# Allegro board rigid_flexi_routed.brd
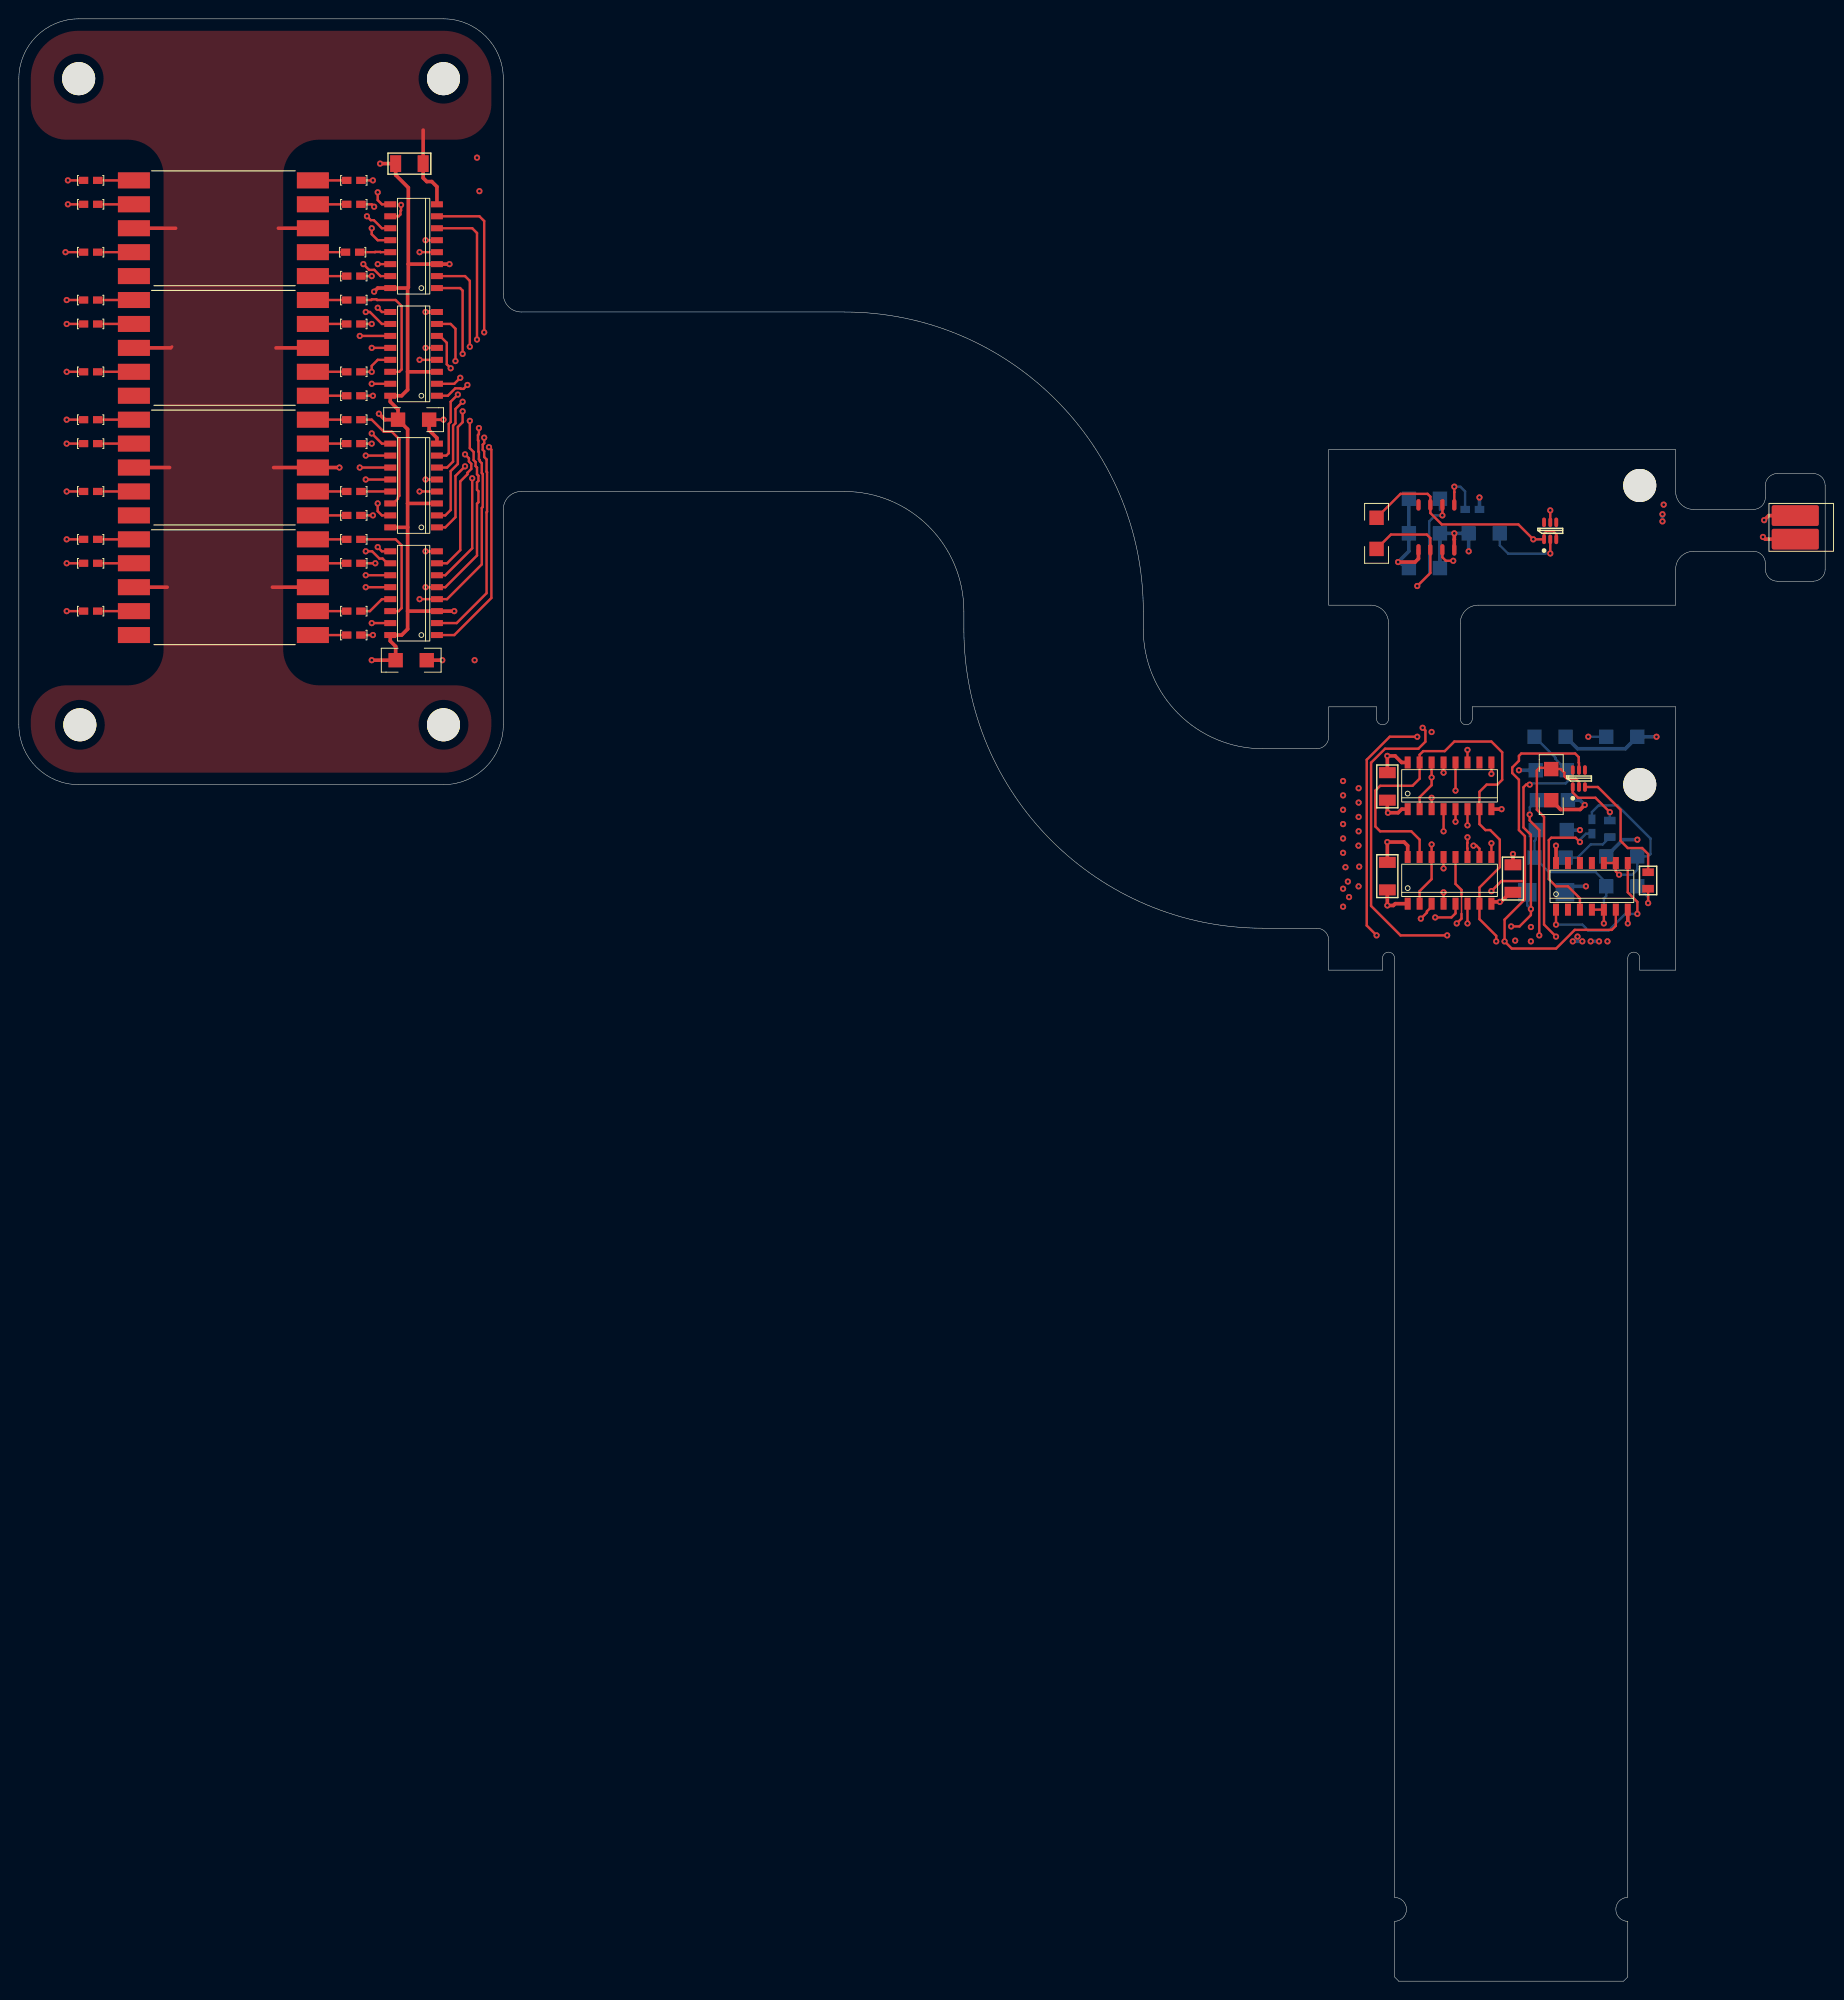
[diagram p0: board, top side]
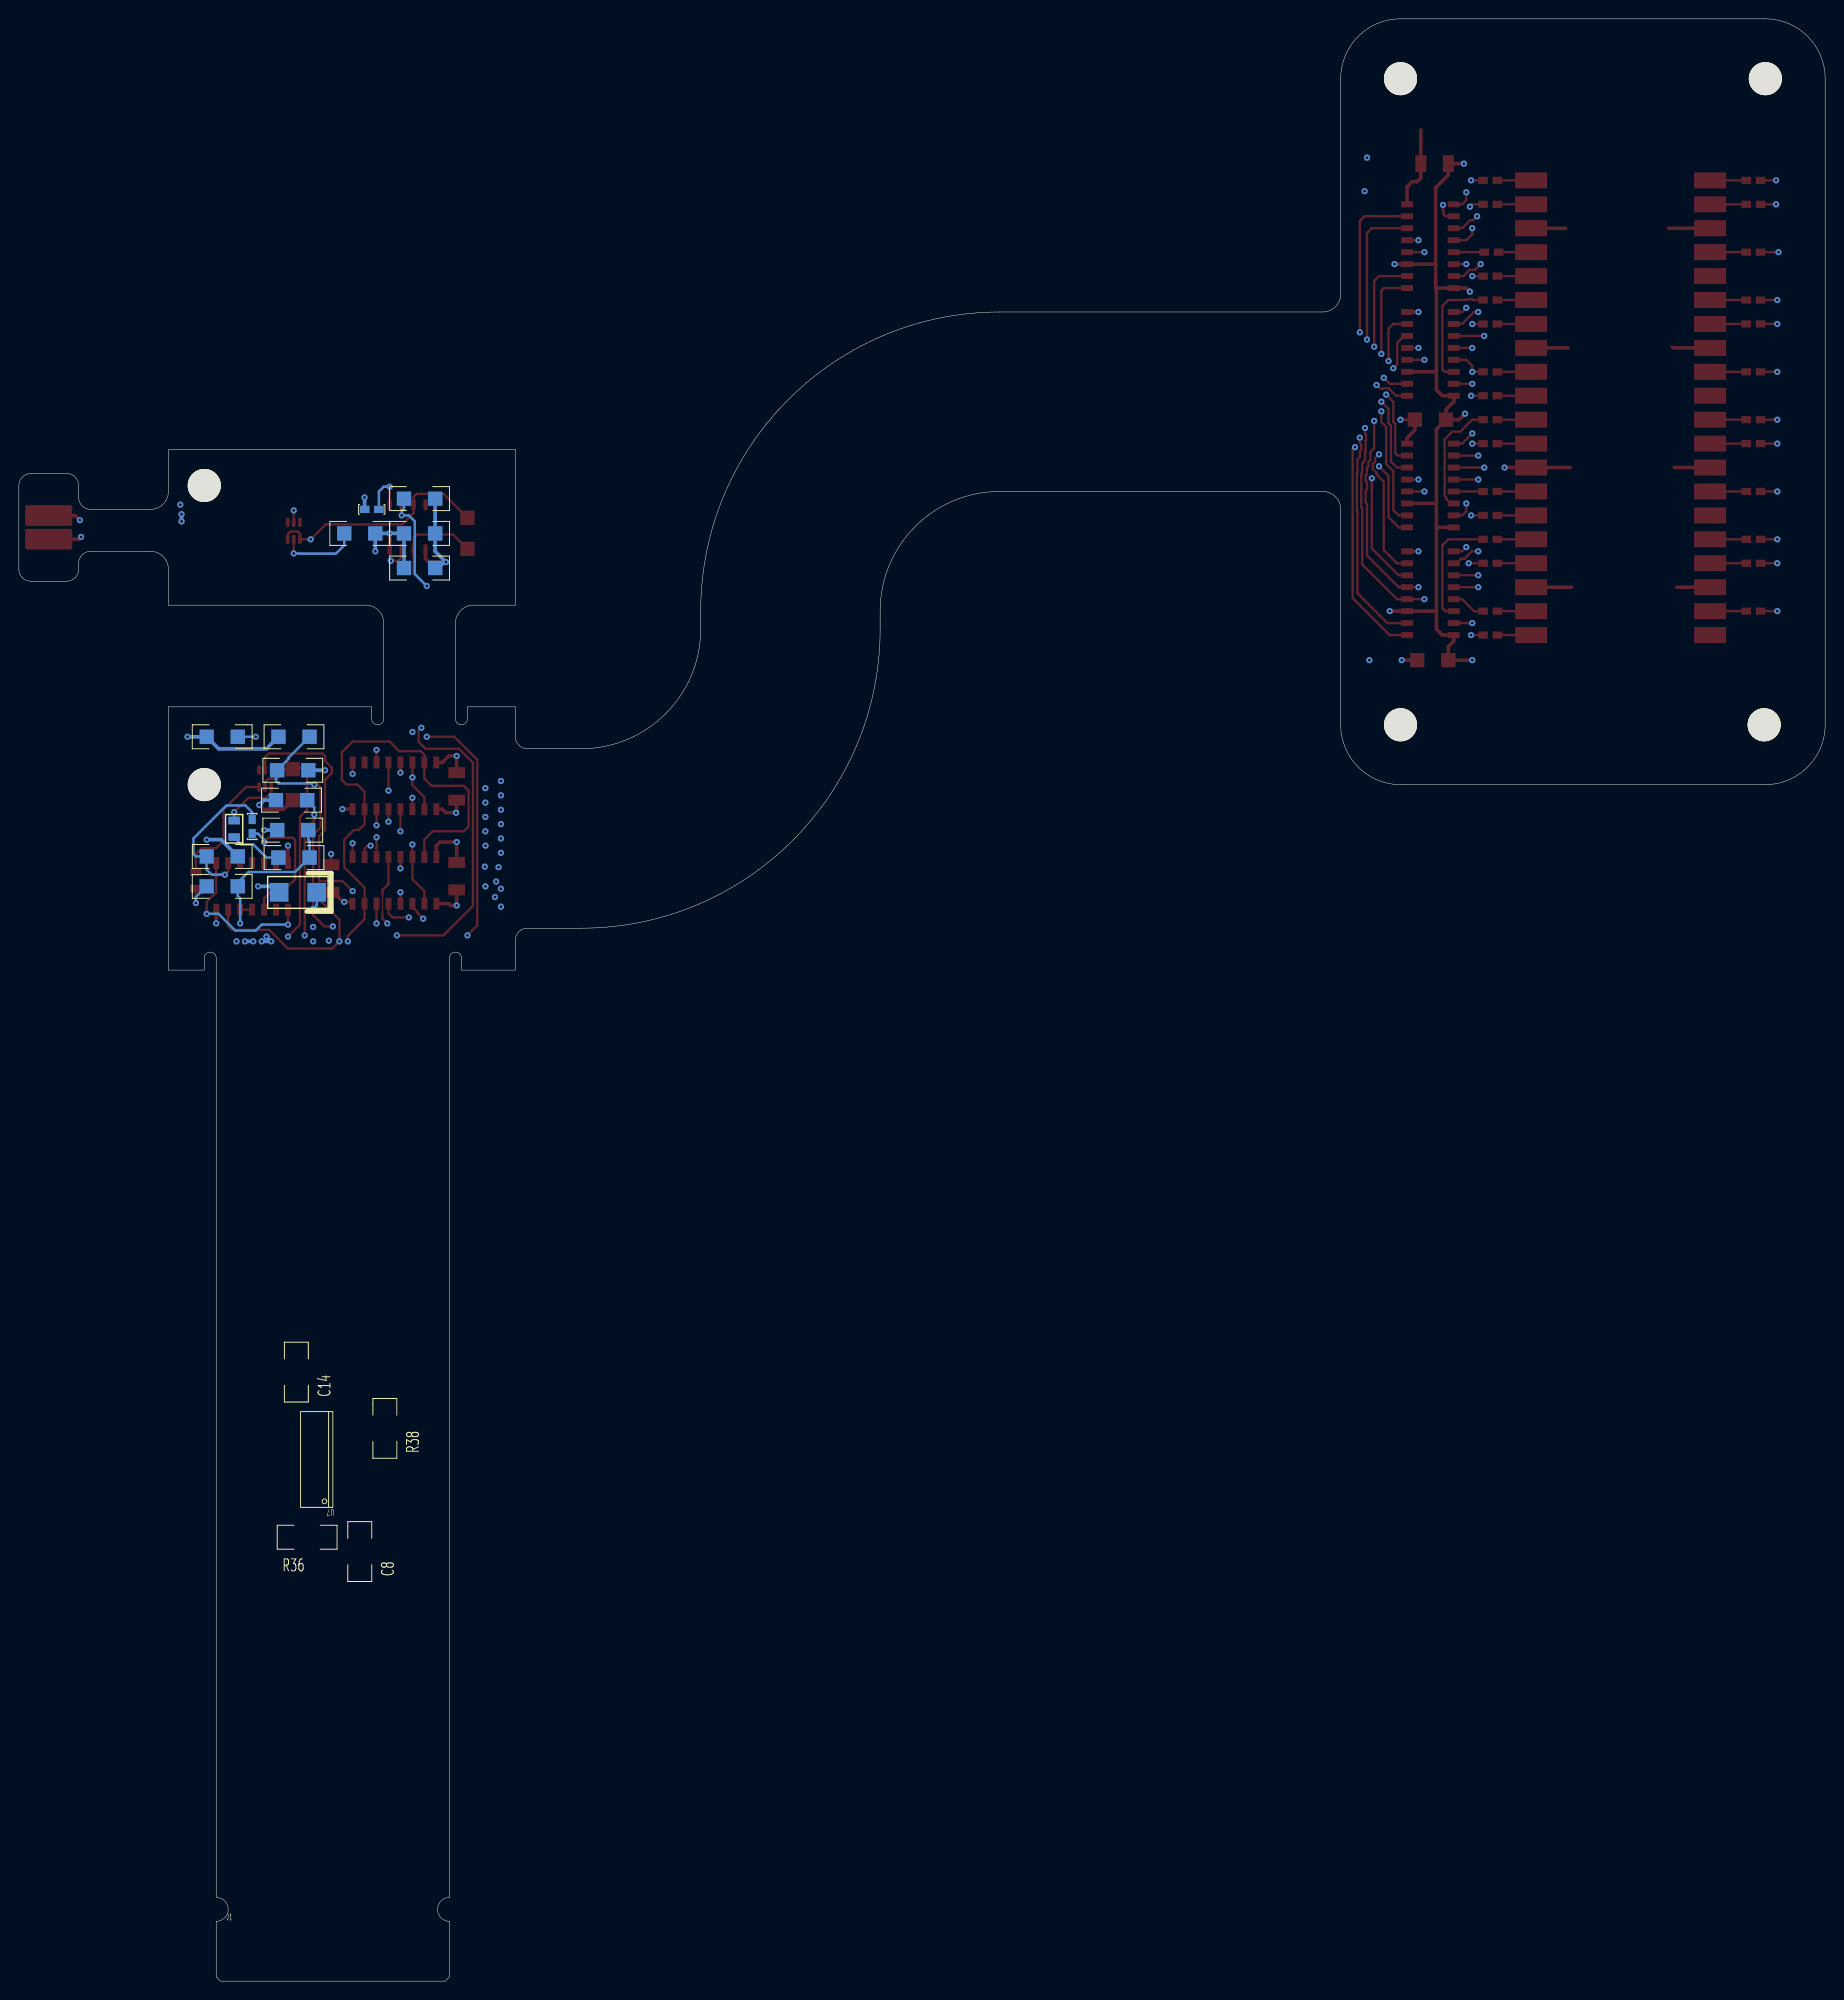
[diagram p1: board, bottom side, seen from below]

Outline 191.77 x 208.28 mm; copper layers: TOP, INT_1, FLEX_1, FLEX_2, INT_4, BOTTOM. Coordinates in mm from the lower left corner of the outline.
Outline path: 0,201.93 0,133.35 arc(1.86,128.86) 6.35,127 45.08,127 arc(49.58,128.86) 51.43,133.35 51.43,156.21 arc(51.99,157.56) 53.34,158.12 87.63,158.12 arc(96.61,154.4) 100.33,145.41 100.33,143.51 arc(109.63,121.06) 132.08,111.76 137.8,111.76 arc(138.69,111.39) 139.06,110.49 139.06,107.31 144.78,107.31 144.78,108.59 arc(145.41,109.22) 146.05,108.59 146.05,8.89 arc(147.32,7.62) 146.05,6.35 146.05,0.45 146.5,0 170.37,0 170.81,0.45 170.81,6.35 arc(169.55,7.62) 170.81,8.89 170.81,108.59 arc(171.45,109.22) 172.08,108.59 172.08,107.31 175.89,107.31 175.89,135.25 154.31,135.25 154.31,133.99 arc(153.67,133.35) 153.03,133.99 153.03,144.14 arc(153.59,145.49) 154.94,146.05 175.89,146.05 175.89,149.86 arc(176.45,151.21) 177.8,151.76 184.15,151.76 arc(185.05,151.39) 185.42,150.5 185.42,149.86 arc(185.79,148.96) 186.69,148.59 190.5,148.59 arc(191.4,148.96) 191.77,149.86 191.77,158.75 arc(191.4,159.65) 190.5,160.02 186.69,160.02 arc(185.79,159.65) 185.42,158.75 185.42,157.48 arc(185.05,156.58) 184.15,156.21 177.8,156.21 arc(176.45,156.77) 175.89,158.12 175.89,162.56 139.06,162.56 139.06,146.05 143.51,146.05 arc(144.86,145.49) 145.41,144.14 145.41,133.99 arc(144.78,133.35) 144.14,133.99 144.14,135.25 139.06,135.25 139.06,132.08 arc(138.69,131.18) 137.8,130.81 132.08,130.81 arc(123.1,134.53) 119.38,143.51 119.38,145.41 arc(110.08,167.87) 87.63,177.17 53.34,177.17 arc(51.99,177.72) 51.43,179.07 51.43,201.93 arc(49.58,206.42) 45.08,208.28 6.35,208.28 arc(1.86,206.42) 0,201.93

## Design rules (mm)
constraint set DEFAULT: min track width 0.254
nets with their own width: min track width 0.381; nets GND

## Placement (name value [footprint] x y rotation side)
B1  -  [BATT1]  188.59 154.31 90 top
C1  -  [A_MC-1206_A]  145.29 115.82 90 top
C2  -  [A_MC-1206_A]  145.29 125.35 90 top
C3  -  [A_MC-1206_A]  158.62 115.57 90 top
C4  -  [A_MC-1206_A]  42.93 192.91 180 top
C5  .001UF  [1206RF_WV_12D]  149.22 149.99 180 bottom
C6  .001UF  [1206RF_WV_12D]  149.22 153.67 180 bottom
C7  .001UF  [1206RF_WV_12D]  149.22 157.35 0 bottom
C8  .001UF  [1206RF_WV_12D#2]  155.57 45.59 90 bottom
C9  .001UF  [1206RF_WV_12D]  162.69 122.17 0 bottom
C10  .001UF  [1206RF_WV_12D]  41.91 165.74 0 top
C11  .001UF  [1206RF_WV_12D]  41.66 140.21 180 top
C12  .1UF  [0603RF_WV_12D]  154.31 156.21 180 bottom
C13  .1UF  [0603RF_WV_12D]  167 122.56 270 bottom
C14  10UF  [1206RF_WV_12D#2]  162.31 64.64 90 bottom
C15  10UF  [1206RF_WV_12D]  162.69 128.52 180 bottom
D1  1N4148  [A_CR-0805]  168.91 123.19 270 bottom
D2  1N4148  [A_CR-0805]  172.97 115.95 90 top
D3  20V  [A_DIODE-157]  160.15 115.57 0 bottom
DSP1  -  [LED-DISPLAY]  21.72 186.06 270 top
DSP2  -  [LED-DISPLAY]  21.72 173.36 270 top
DSP3  -  [LED-DISPLAY]  21.72 160.66 270 top
DSP4  -  [LED-DISPLAY]  21.72 147.95 270 top
J1  -  [CONN10]  169.8 3.56 180 bottom
NOREF  -  [unnamed]  172.08 127 0 top
NOREF#2  -  [unnamed]  6.48 133.35 0 top
NOREF#3  -  [unnamed]  45.08 201.93 0 top
NOREF#4  -  [unnamed]  172.08 158.75 0 top
NOREF#5  -  [unnamed]  45.08 133.35 0 top
NOREF#6  -  [unnamed]  6.35 201.93 0 top
R1  390  [0603RF_WV_12D]  7.62 191.13 0 top
R2  390  [0603RF_WV_12D]  35.56 191.13 0 top
R3  390  [0603RF_WV_12D]  7.62 188.59 0 top
R4  390  [0603RF_WV_12D]  35.56 188.59 0 top
R5  390  [0603RF_WV_12D]  7.62 183.51 0 top
R6  390  [0603RF_WV_12D]  35.43 183.51 0 top
R7  390  [0603RF_WV_12D]  35.56 180.97 0 top
R8  390  [0603RF_WV_12D]  7.62 178.44 0 top
R9  390  [0603RF_WV_12D]  35.56 178.44 0 top
R10  390  [0603RF_WV_12D]  7.62 175.89 0 top
R11  390  [0603RF_WV_12D]  35.56 175.89 0 top
R12  390  [0603RF_WV_12D]  7.62 170.81 0 top
R13  390  [0603RF_WV_12D]  35.56 170.81 0 top
R14  390  [0603RF_WV_12D]  35.56 168.28 0 top
R15  390  [0603RF_WV_12D]  7.62 165.74 0 top
R16  390  [0603RF_WV_12D]  35.56 165.74 0 top
R17  390  [0603RF_WV_12D]  7.62 163.19 0 top
R18  390  [0603RF_WV_12D]  35.56 163.19 0 top
R19  390  [0603RF_WV_12D]  7.62 158.12 0 top
R20  390  [0603RF_WV_12D]  35.56 158.12 0 top
R21  390  [0603RF_WV_12D]  35.56 155.57 0 top
R22  390  [0603RF_WV_12D]  7.62 153.03 0 top
R23  390  [0603RF_WV_12D]  35.56 153.03 0 top
R24  390  [0603RF_WV_12D]  7.62 150.5 0 top
R25  390  [0603RF_WV_12D]  35.56 150.5 0 top
R26  390  [0603RF_WV_12D]  7.62 145.41 0 top
R27  390  [0603RF_WV_12D]  35.56 145.41 0 top
R28  390  [0603RF_WV_12D]  35.56 142.88 0 top
R29  15K  [1206RF_WV_12D]  170.18 116.2 180 bottom
R30  15K  [1206RF_WV_12D]  162.56 119.25 180 bottom
R31  10K  [1206RF_WV_12D]  144.14 153.67 270 top
R32  10K  [1206RF_WV_12D]  155.57 153.67 0 bottom
R33  10K  [1206RF_WV_12D]  162.69 127 90 top
R34  10K  [1206RF_WV_12D]  170.18 119.38 0 bottom
R35  10K  [1206RF_WV_12D]  162.56 132.08 0 bottom
R36  100K  [1206RF_WV_12D#2]  161.16 47.12 180 bottom
R37  100K  [1206RF_WV_12D]  162.81 125.35 180 bottom
R38  12K  [1206RF_WV_12D#2]  152.91 58.67 90 bottom
R39  3.3K  [1206RF_WV_12D]  170.18 132.08 180 bottom
RV1  10K  [A_SOT363]  164.97 126.75 0 top
RV2  10K  [A_SOT363]  161.93 153.03 0 top
U1  ***  [SOIC16]  41.91 184.15 180 top
U2  ***  [SOIC16]  41.91 172.72 180 top
U3  ***  [SOIC16]  41.91 158.75 180 top
U4  ***  [SOIC16]  41.91 147.32 180 top
U5  ***  [SOIC16]  151.89 126.87 90 top
U6  ***  [SOIC16]  151.89 116.84 90 top
U7  -  [SOIC16#2]  160.15 55.37 0 bottom
U8  -  [SOIC8]  150.5 154.31 90 top
U9  ***  [SOIC14]  167.64 116.2 90 top

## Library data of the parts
B1 = BATT1
C1-C4 = CAP15UF
C5-C11 = CAP: tolerance: 10%
C12-C15 = CAP
D1 D2 = 1N4148
D3 = 20V-RCT
DSP1-DSP4 = DISPLAY-LED
J1 = CONN10
R1-R28 = RES_RES0201_DISCRETE_0.3 MM_10K
R29-R39 = RES: tolerance: 5%
RV1 RV2 = VRES
U1-U4 = CD4511
U5 U6 = CD4518
U7 = CD4098: User Part Number: ***; Tolerance: ***
U8 = NE555
U9 = SN7400

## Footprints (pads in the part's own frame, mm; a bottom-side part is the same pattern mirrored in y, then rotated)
0603RF_WV_12D
  rect 1.016x0.762 smd: 1(-0.762,0) 2(0.762,0)
1206RF_WV_12D
  rect 1.524x1.524 smd: 1(-1.651,0) 2(1.651,0)
A_CR-0805
  rect 0.813x1.219 smd: 1(0,0) 2(1.753,0)
A_DIODE-157
  rect 1.981x1.981 smd: 1(0,0) 2(3.988,0)
A_MC-1206_A
  rect 1.168x1.778 smd: 1(0,0) 2(2.921,0)
A_SOT363
  custom 0.102x0.102 smd: 1(0,0) 2(0.66,0) 3(1.295,0) 4(1.295,1.803) 5(0.66,1.803) 6(0,1.803)
BATT1
  rrect 2.2x5 smd: 1(-1.25,0) 2(1.25,0)
LED-DISPLAY
  rect 1.7x3.4 smd: 1(-5.08,-9.5) 2(-2.54,-9.5) 3(0,-9.5) 4(2.54,-9.5) 5(5.08,-9.5) 6(5.08,9.5) 7(2.54,9.5) 8(0,9.5) 9(-2.54,9.5) 10(-5.08,9.5)
SOIC8
  oval 1.23x0.46 smd: 1(-2.39,1.9) 2(-2.39,0.64) 3(-2.39,-0.63) 4(-2.39,-1.9) 5(2.39,-1.9) 6(2.39,-0.64) 7(2.39,0.64) 8(2.39,1.9)
SOIC14
  rect 1.27x0.635 smd: 1(-2.477,4.445) 2(-2.477,3.175) 3(-2.477,1.905) 4(-2.477,0.635) 5(-2.477,-0.635) 6(-2.477,-1.905) 7(-2.477,-3.175) 8(2.477,-3.175) 9(2.477,-1.905) 10(2.477,-0.635) 11(2.477,0.635) 12(2.477,1.905) 13(2.477,3.175) 14(2.477,4.445)
SOIC16
  rect 1.27x0.635 smd: 1(-2.477,4.445) 2(-2.477,3.175) 3(-2.477,1.905) 4(-2.477,0.635) 5(-2.477,-0.635) 6(-2.477,-1.905) 7(-2.477,-3.175) 8(-2.477,-4.445) 9(2.477,-4.445) 10(2.477,-3.175) 11(2.477,-1.905) 12(2.477,-0.635) 13(2.477,0.635) 14(2.477,1.905) 15(2.477,3.175) 16(2.477,4.445)
unnamed
  round 3.505 hole 3.505 unplated: (0,0)

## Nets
GND: B1.2 C1.1 C2.1 C3.1 C4.1 C5.2 C6.2 C7.1 C9.2 C10.2 C11.1 C12.1 C15.2 D3.2 DSP1.3 DSP1.8 DSP2.3 DSP2.8 DSP3.3 DSP3.8 DSP4.3 DSP4.8 U1.8 U2.8 U3.8 U4.8 U5.1 U5.8 U6.1 U6.8 U8.1 U9.7
VCC: B1.1 C1.2 C2.2 C3.2 C4.2 C5.1 C6.1 C10.1 C11.2 R32.1 R33.1 R34.1 R35.2 R37.1 R39.1 U1.3 U1.16 U2.3 U2.16 U3.3 U3.16 U4.3 U4.16 U5.16 U6.16 U8.4 U9.14
A_1: U1.7 U5.11
A_2: U2.7 U5.3
A_3: U3.7 U6.11
A_4: U4.7 U6.3
B_1: U1.1 U5.12
B_2: U2.1 U5.4
B_3: U3.1 U6.12
B_4: U4.1 U6.4
C_1: U1.2 U5.13
C_2: U2.2 U5.5
C_3: U3.2 U6.13
C_4: U4.2 U6.5
D_1: U1.6 U5.2 U5.14
D_2: U2.6 U5.6
D_3: U3.6 U6.2 U6.14
D_4: U4.6 U6.6
F1_1: R1.1 U1.9
F1_2: R8.1 U2.9
F1_3: R15.1 U3.9
F1_4: R22.1 U4.9
F2_1: R3.1 U1.10
F2_2: R10.1 U2.10
F2_3: R17.1 U3.10
F2_4: R24.1 U4.10
F3_1: R5.1 U1.11
F3_2: R12.1 U2.11
F3_3: R19.1 U3.11
F3_4: R26.1 U4.11
F4_1: R7.2 U1.12
F4_2: R14.2 U2.12
F4_3: R21.2 U3.12
F4_4: R28.2 U4.12
F5_1: R6.2 U1.13
F5_2: R13.2 U2.13
F5_3: R20.2 U3.13
F5_4: R27.2 U4.13
F6_1: R4.2 U1.15
F6_2: R11.2 U2.15
F6_3: R18.2 U3.15
F6_4: R25.2 U4.15
F7_1: R2.2 U1.14
F7_2: R9.2 U2.14
F7_3: R16.2 U3.14
F7_4: R23.2 U4.14
INT: RV1.5 U1.4 U2.4 U3.4 U4.4 U9.6
INT3: C15.1 D3.1 R35.1
INT_N: R32.2 RV2.2
LG1: D1.1 RV1.1
LG2: D2.2 RV1.3
LG3: D1.2 R30.1
LG4: D2.1 R29.1
N1_1: DSP1.1 R1.2
N1_2: DSP2.1 R8.2
N1_3: DSP3.1 R15.2
N1_4: DSP4.1 R22.2
N2_1: DSP1.2 R3.2
N2_2: DSP2.2 R10.2
N2_3: DSP3.2 R17.2
N2_4: DSP4.2 R24.2
N3_1: DSP1.4 R5.2
N3_2: DSP2.4 R12.2
N3_3: DSP3.4 R19.2
N3_4: DSP4.4 R26.2
N4_1: DSP1.6 R7.1
N4_2: DSP2.6 R14.1
N4_3: DSP3.6 R21.1
N4_4: DSP4.6 R28.1
N5_1: DSP1.7 R6.1
N5_2: DSP2.7 R13.1
N5_3: DSP3.7 R20.1
N5_4: DSP4.7 R27.1
N6_1: DSP1.9 R4.1
N6_2: DSP2.9 R11.1
N6_3: DSP3.9 R18.1
N6_4: DSP4.9 R25.1
N7_1: DSP1.10 R2.1
N7_2: DSP2.10 R9.1
N7_3: DSP3.10 R16.1
N7_4: DSP4.10 R23.1
NET000: U1.5 U2.5 U3.5 U4.5
NET001: U5.7 U5.15 U6.7 U6.15
NET002: U8.3
NET003: C7.2 R31.2 U8.2 U8.6
NET004: U5.9 U6.9 U9.1 U9.8
NET005: C9.1 R29.2 R30.2 U9.4 U9.5
SIG_IN_N: R33.2 RV1.2
TM1: R39.2 RV2.5
TM2: R31.1 RV2.1 RV2.3 U8.7
TM3: C12.2 U8.5
TM6: R37.2
VC1: C13.2 U9.3
VC2: C13.1 R34.2 U9.9 U9.10

Pads without a net: DSP1 5; DSP2 5; DSP3 5; DSP4 5; RV1 4 6; RV2 4 6; U5 10; U6 10; U8 8; U9 2 11 12 13

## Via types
v1: diameter 0.66, hole 0.305, TOP to BOTTOM, 182 vias

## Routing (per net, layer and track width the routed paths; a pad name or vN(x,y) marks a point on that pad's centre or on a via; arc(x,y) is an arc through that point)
GND: length 95.3
  TOP w0.305: C10.2 v1(45.08,165.74) ; 16.26,173.48 16.13,173.36 ; U4.8 v1(43.18,151.76)
  TOP w0.381: v1(185.29,155.07) 185.78,155.56 B1.2 ; DSP2.8 27.3,173.36 ; U5.8 v1(157.42,124.4) ; DSP1.3 16.64,186.06 ; 27.05,160.66 DSP3.8 v1(34.04,160.66) ; U6.8 156.53,114.55 v1(157.23,114.55) 157.35,114.55 158.37,115.57 C3.1 ; DSP4.8 26.92,147.95 ; C1.1 v1(145.29,114.17) 145.94,114.17 146.13,114.36 U6.1 ; C2.1 145.29,124.08 v1(145.35,124.02) 146.43,124.02 146.81,124.4 U5.1 ; 42.93,196.47 C4.1 42.93,191.39 43.31,191.01 43.84,191.01 44.39,190.46 U1.8 ; 148.59,151.92 148.59,150.98 148.23,150.62 v1(146.43,150.62) ; C11.1 v1(44.96,140.21) ; DSP1.8 27.56,186.06 ; U2.8 v1(43.18,177.17) ; U3.8 44.39,163.79 43.56,164.62 C10.2 ; 16.13,173.36 DSP2.3 ; DSP3.3 16,160.66 ; DSP4.3 15.75,147.95 ; U9.7 v1(170.81,112.27)
  FLEX_2 w0.381: 174.5,156.02 174.5,156.4 174.88,156.78 174.88,157.35 174.62,157.1 v1(174.62,156.72)
  FLEX_2 w0.5: 162.62,57.28 161.54,57.28 ; 157.67,53.47 158.75,53.47 ; 157.67,59.82 158.75,59.82 ; 157.67,56.01 158.75,56.01 ; 162.62,54.74 161.54,54.74
  BOTTOM w0.381: C15.2 v1(159.26,128.52) ; v1(166.37,116.2) 164.9,116.2 D3.2 ; C5.2 v1(146.43,150.62) 147.57,151.76 C6.2 C7.1 ; C9.2 v1(165.74,122.17) ; v1(174.5,154.94) v1(174.5,155.7) ; C12.1 v1(155.07,157.48)
VCC: length 399.3
  TOP w0.381: C10.1 41.27,164.72 41.27,156.84 ; C10.1 40.26,166.81 39.43,167.64 39.43,168.28 40.64,168.28 41.27,168.91 41.27,170.81 ; C10.1 38.86,165.74 v1(38.23,166.37) ; C3.2 v1(158.62,119.63) ; v1(45.72,182.25) U1.3 41.35,182.25 ; 41.27,145.41 U4.3 v1(46.23,145.41) ; 41.27,145.41 41.27,154.31 ; 41.27,145.41 41.27,143.51 40.64,142.88 U4.16 39.43,142.24 40,141.67 C11.2 v1(37.46,140.21) ; 41.27,154.31 U3.16 ; 41.27,154.31 41.27,156.84 ; B1.1 185.4,153.06 v1(185.17,153.29) ; C1.2 v1(145.29,120.9) 147.07,120.9 147.45,120.52 U6.16 ; v1(166.24,124.84) 165.76,124.36 163.67,124.36 R33.1 ; U3.3 41.27,156.84 ; 41.27,170.81 U2.3 ; 41.27,170.81 41.27,179.7 ; v1(37.72,179.32) 38.1,179.7 U1.16 41.27,179.7 ; 41.27,179.7 41.35,179.78 41.35,182.25 ; v1(152.4,153.67) 152.4,153.02 152.39,153.02 152.39,151.92 ; U5.16 146.81,129.35 146.11,130.05 v1(145.29,130.05) C2.2 ; U9.14 v1(163.19,120.52) ; v1(38.35,192.91) C4.2 40,191.71 41.35,190.36 41.35,182.25
  FLEX_1 w0.5: 162.81,48.89 165.99,48.89
  FLEX_1 w1.27: 49.66,179.83 49.66,178.28 50.91,177.02 arc(52,176.19) 53.34,175.89 87.63,175.89 arc(109.18,166.97) 118.11,145.41 118.11,143.51 arc(122.2,133.63) 132.08,129.54 139.32,129.54 141.61,131.83 ; 49.15,146.05 49.15,155.19 49.66,155.7 49.66,156.72 50.42,157.48 50.42,157.66 50.65,157.89 arc(51.8,158.99) 53.34,159.38 87.63,159.38 arc(97.51,155.29) 101.6,145.41 101.6,143.51 arc(110.53,121.96) 132.08,113.03 137.8,113.03 arc(139.53,112.34) 140.33,110.66 140.35,110.64 141.86,110.74
  FLEX_2 w0.381: v1(167.77,110.36) v1(168.66,110.36) ; v1(165.99,110.36) v1(166.88,110.36)
  FLEX_2 w0.5: 162.81,47.12 162.81,50.04 162.62,50.23 162.62,50.93
  BOTTOM w0.381: C5.1 C6.1 v1(152.4,153.67) 153.92,153.67 v1(153.92,151.76) ; v1(173.86,132.08) R39.1 170.56,130.81 165.48,130.81 R35.2 ; R34.1 170.31,121.16 v1(171.83,121.16) ; v1(165.99,110.36) v1(164.97,110.36) v1(165.48,110.87) ; v1(166.88,110.36) v1(167.77,110.36) ; R37.1 165.74,125.35 v1(166.24,124.84)
  vias: v1(48.39,140.21) v1(48.64,193.55) v1(48.89,189.99)
A_1: length 153.5
  TOP w0.254: U5.11 v1(153.8,130.68) ; v1(49.4,175.01) 49.4,186.82 48.89,187.32 U1.7
  FLEX_1 w0.254: v1(140.59,127.38) 132.08,127.38 arc(120.68,132.11) 115.95,143.51 115.95,145.41 arc(107.66,165.44) 87.63,173.74 59.67,173.74 arc(59.37,173.8) 59.1,173.97 59.07,174.01 arc(58.81,174.18) 58.5,174.24 50.16,174.24 v1(49.4,175.01)
  INT_4 w0.254: v1(153.8,130.68) 153.16,131.32 142.62,131.32 140.59,129.29 v1(140.59,127.38)
A_2: length 138.7
  TOP w0.254: U5.3 v1(149.99,125.6) ; U2.7 45.85,175.89 46.35,175.39 v1(46.35,171.96)
  FLEX_1 w0.254: v1(46.35,171.96) 46.86,171.45 49.4,171.45 49.66,171.2 57.24,171.2 arc(57.55,171.13) 57.81,170.96 57.84,170.92 arc(58.1,170.75) 58.41,170.69 87.63,170.69 arc(105.5,163.29) 112.9,145.41 112.9,143.51 arc(118.52,129.95) 132.08,124.33 v1(140.59,124.33)
  INT_4 w0.254: v1(140.59,124.33) 142.75,124.33 144.02,125.6 v1(149.99,125.6)
A_3: length 144.7
  TOP w0.254: U6.11 153.8,120.22 153.77,120.25 153.77,120.8 153.8,120.82 v1(153.8,121.41) ; v1(46.61,168.4) 45.85,167.64 45.85,165.49 45.64,165.29 45.64,162.18 45.39,161.93 U3.7
  FLEX_1 w0.254: v1(46.61,168.4) 47.88,168.4 48.13,168.15 55.15,168.15 arc(55.63,168.05) 56.04,167.78 56.44,167.38 arc(56.86,167.1) 57.34,167 87.63,167 arc(103.35,160.5) 109.85,144.78 109.85,143.51 arc(116.36,127.79) 132.08,121.28 v1(140.59,121.28)
  INT_4 w0.254: v1(153.8,121.41) 153.16,121.41 153.09,121.34 150.31,121.34 150.28,121.36 148.26,121.36 147.95,121.67 143.64,121.67 143.26,121.28 v1(140.59,121.28)
A_4: length 146.4
  TOP w0.254: v1(148.84,112.78) 149.49,113.42 149.49,113.55 149.99,114.05 U6.3 ; U4.7 45.47,150.5 46.86,151.89 46.86,159.18 47.62,159.94 47.62,160.1 48.03,160.51 48.03,161.06 47.78,161.3 47.78,161.64 v1(47.37,162.05)
  FLEX_1 w0.254: v1(47.37,162.05) 49.15,162.05 49.4,161.8 50.42,161.8 50.83,162.21 arc(50.94,162.28) 51.06,162.31 87.63,162.31 arc(99.57,157.36) 104.52,145.41 104.52,143.51 arc(112.59,124.02) 132.08,115.95 v1(140.59,115.95)
  INT_4 w0.254: v1(148.84,112.78) 146.26,115.36 142.07,115.36 141.48,115.95 v1(140.59,115.95)
B_1: length 146.2
  TOP w0.254: U5.12 v1(152.53,126.37) ; U1.1 46.85,179.7 47.12,179.44 v1(47.12,172.72)
  FLEX_1 w0.254: v1(47.12,172.72) 47.88,171.96 57.55,171.96 arc(57.86,171.9) 58.12,171.72 58.16,171.69 arc(58.42,171.51) 58.73,171.45 87.63,171.45 arc(106.04,163.82) 113.66,145.41 113.66,143.51 arc(119.06,130.49) 132.08,125.09 v1(142.24,125.09)
  INT_4 w0.254: v1(142.24,125.09) 143.51,126.37 v1(152.53,126.37)
B_2: length 137
  TOP w0.254: U5.4 v1(151.26,122.05) ; 44.39,168.28 45.55,168.28 46.34,169.06 46.88,169.06 46.94,169 47.21,169 v1(47.62,169.42)
  FLEX_1 w0.254: v1(47.62,169.42) 48.13,168.91 55.46,168.91 arc(55.95,168.81) 56.36,168.54 56.76,168.14 arc(57.17,167.86) 57.66,167.77 87.63,167.77 arc(103.88,161.03) 110.62,144.78 110.62,143.51 arc(116.9,128.33) 132.08,122.05 v1(142.24,122.05)
  INT_4 w0.254: v1(142.24,122.05) 142.88,122.05 142.95,122.12 150.55,122.12 150.62,122.05 v1(151.26,122.05)
B_3: length 150
  TOP w0.152: 153.16,115.32 153.16,113.28
  TOP w0.254: v1(152.65,112.27) 153.16,112.78 153.16,113.28 ; 153.16,115.32 153.16,115.82 152.53,116.46 U6.12 ; U3.1 45.28,154.31 46.35,155.38 46.35,159.77 v1(47.37,160.78)
  FLEX_1 w0.254: v1(141.22,115.06) 140.2,115.06 140.12,114.99 139.53,114.99 139.33,115.19 132.08,115.19 arc(112.05,123.48) 103.76,143.51 103.76,145.41 arc(99.03,156.82) 87.63,161.54 51.06,161.54 arc(50.94,161.52) 50.83,161.45 arc(50.66,161.33) 50.45,161.29 48.64,161.29 48.13,160.78 v1(47.37,160.78)
  INT_4 w0.254: v1(152.65,112.27) 151.88,112.27 151.68,112.06 146.13,112.06 144.91,113.28 143,113.28 v1(141.22,115.06)
B_4: length 154.1
  TOP w0.254: U6.4 v1(151.26,115.57) ; U4.1 46.23,142.88 50.16,146.81 50.16,162.56 v1(49.91,162.81)
  FLEX_1 w0.254: v1(141.1,116.71) 132.08,116.71 arc(113.13,124.56) 105.28,143.51 105.28,145.41 arc(100.11,157.9) 87.63,163.07 50.55,163.07 arc(50.43,163.04) 50.32,162.97 arc(50.15,162.86) 49.94,162.81 v1(49.91,162.81)
  INT_4 w0.254: v1(141.1,116.71) 141.74,116.71 141.94,116.91 149.15,116.91 150.5,115.57 v1(151.26,115.57)
C_1: length 145.1
  TOP w0.254: U1.2 47.37,180.97 47.88,180.47 v1(47.88,173.48) ; U5.13 v1(151.26,128.27)
  FLEX_1 w0.254: v1(140.59,125.86) 132.08,125.86 arc(119.6,131.03) 114.43,143.51 114.43,145.41 arc(106.58,164.36) 87.63,172.21 59.04,172.21 arc(58.74,172.27) 58.47,172.45 58.44,172.48 arc(58.18,172.66) 57.87,172.72 49.15,172.72 arc(48.68,172.81) 48.28,173.08 v1(47.88,173.48)
  INT_4 w0.254: v1(140.59,125.86) 141.48,126.75 141.48,128.14 142.11,128.78 150.75,128.78 v1(151.26,128.27)
C_2: length 137.5
  TOP w0.254: U5.5 v1(152.53,123.06) ; v1(46.86,170.18) 46.23,169.55 U2.2
  FLEX_1 w0.254: v1(46.86,170.18) 47.5,170.18 47.55,170.13 48.44,170.13 48.68,169.88 arc(48.92,169.73) 49.19,169.67 56.61,169.67 arc(56.91,169.61) 57.18,169.44 57.21,169.4 arc(57.47,169.23) 57.78,169.16 87.63,169.16 arc(104.42,162.21) 111.38,145.41 111.38,143.51 arc(117.44,128.87) 132.08,122.81 v1(140.59,122.81)
  INT_4 w0.254: v1(152.53,123.06) 149.1,123.06 148.83,122.8 144.85,122.8 144.83,122.81 v1(140.59,122.81)
C_3: length 145.7
  TOP w0.254: U3.2 45.28,155.57 45.85,156.15 45.85,160.27 46.61,161.04 46.61,164.96 47.12,165.47 v1(47.12,166.62) ; U6.13 v1(151.26,118.11)
  FLEX_1 w0.254: v1(140.59,119.76) 132.08,119.76 arc(115.29,126.72) 108.33,143.51 108.33,144.65 arc(102.27,159.29) 87.63,165.35 56.71,165.35 arc(56.22,165.45) 55.81,165.73 55.29,166.25 arc(54.87,166.53) 54.39,166.62 v1(47.12,166.62)
  INT_4 w0.254: v1(151.26,118.11) 150.37,119 143.26,119 142.49,119.76 v1(140.59,119.76)
C_4: length 157.9
  TOP w0.254: U6.5 152.53,113.33 152.1,112.9 v1(150.37,112.9) ; v1(49.4,163.83) 49.4,163.24 49.25,163.09 49.25,162.54 49.4,162.39 49.4,161.77 49.66,161.52 49.66,160.22 49.71,160.16 49.71,155.96 49.66,155.91 49.66,147.32 46.48,144.14 44.39,144.14
  FLEX_1 w0.254: v1(49.4,163.83) 87.63,163.83 arc(100.65,158.44) 106.04,145.41 106.04,143.51 arc(113.67,125.1) 132.08,117.47 140.96,117.47 141.01,117.42 141.65,117.42 142.24,116.84 v1(142.24,116.2)
  INT_4 w0.254: v1(142.24,116.2) 148.21,116.2 150.37,114.05 v1(150.37,112.9)
D_1: length 150.7
  TOP w0.254: U5.14 v1(149.99,127.76) 149.99,126.94 148.72,125.67 U5.2 ; U1.6 48.13,186.06 48.64,185.55 v1(48.64,174.24)
  FLEX_1 w0.254: v1(48.64,174.24) 49.04,173.84 arc(49.44,173.58) 49.92,173.48 58.18,173.48 arc(58.49,173.42) 58.75,173.25 58.79,173.21 arc(59.05,173.04) 59.36,172.97 87.63,172.97 arc(107.12,164.9) 115.19,145.41 115.19,143.51 arc(120.14,131.57) 132.08,126.62 v1(142.24,126.62)
  INT_4 w0.254: v1(142.24,126.62) 143.38,127.76 v1(149.99,127.76)
D_2: length 144
  TOP w0.254: U5.6 v1(153.8,122.68) ; v1(45.85,171.2) 45.43,171.61 45.43,173.9 44.7,174.62 U2.6
  FLEX_1 w0.254: v1(142.24,123.57) 132.08,123.57 arc(117.98,129.41) 112.14,143.51 112.14,145.41 arc(104.96,162.75) 87.63,169.93 58.1,169.93 arc(57.79,169.99) 57.53,170.16 57.49,170.2 arc(57.23,170.37) 56.92,170.43 49.48,170.43 arc(49.17,170.5) 48.91,170.67 48.64,170.94 46.62,170.94 46.37,171.2 v1(45.85,171.2)
  INT_4 w0.254: v1(153.8,122.68) 153.8,124.21 153.42,124.59 147.57,124.59 147.19,124.97 144.91,124.97 143.51,123.57 v1(142.24,123.57)
D_3: length 145.9
  TOP w0.254: U6.2 148.72,115.7 149.99,116.97 U6.14 v1(149.99,120.65) ; v1(47.12,167.64) 46.35,166.88 46.35,165.35 46.1,165.1 46.1,161.29 45.47,160.66 U3.6
  FLEX_1 w0.254: v1(47.12,167.64) 48.64,167.64 48.89,167.39 54.83,167.39 arc(55.32,167.29) 55.73,167.01 56.13,166.62 arc(56.54,166.34) 57.03,166.24 87.63,166.24 arc(102.81,159.96) 109.09,144.78 109.09,143.51 arc(115.83,127.26) 132.08,120.52 v1(142.23,120.52)
  INT_4 w0.254: v1(149.99,120.65) 149.54,120.2 149.41,120.2 149.35,120.14 143.24,120.14 142.86,120.52 v1(142.23,120.52)
D_4: length 150.9
  TOP w0.254: v1(48.13,159.51) 48.13,152.08 45.28,149.22 U4.6 ; U6.6 v1(153.8,112.27)
  FLEX_1 w0.254: v1(140.59,114.05) 140.08,114.05 139.7,114.43 132.08,114.43 arc(111.52,122.95) 103,143.51 103,145.41 arc(98.5,156.28) 87.63,160.78 49.4,160.78 v1(48.13,159.51)
  INT_4 w0.254: v1(153.8,112.27) 153.8,111.63 152.4,110.24 150.47,110.24 149.1,111.61 145.69,111.61 144.53,112.78 141.86,112.78 v1(140.59,114.05)
F1_1: length 37.4
  TOP w0.254: U1.9 38.54,188.59 38.1,189.04 v1(38.1,189.87) ; R1.1 v1(5.21,191.13)
  FLEX_1 w0.254: v1(5.21,191.13) 6.48,189.87 v1(38.1,189.87)
F1_2: length 36.9
  TOP w0.254: v1(38.1,177.61) 38.54,177.17 U2.9 ; R8.1 v1(5.08,178.44)
  FLEX_1 w0.254: v1(5.08,178.44) 5.91,177.61 36.27,177.61 36.54,177.88 37.12,177.88 37.39,177.61 v1(38.1,177.61)
F1_3: length 37.2
  TOP w0.254: U3.9 38.54,163.19 v1(37.46,164.27) ; R15.1 v1(5.08,165.74)
  FLEX_1 w0.254: v1(5.08,165.74) 6.54,164.27 v1(37.46,164.27)
F1_4: length 36.7
  TOP w0.254: v1(38.1,152.21) 38.54,151.76 U4.9 ; R22.1 v1(5.08,153.03)
  FLEX_1 w0.254: v1(5.08,153.03) 37.27,153.03 v1(38.1,152.21)
F2_1: length 39.9
  TOP w0.254: R3.1 v1(5.21,188.59) ; U1.10 40.32,187.32 40.51,187.52 40.51,187.88 40.58,187.95 v1(40.58,188.53)
  FLEX_1 w0.254: v1(5.21,188.59) 5.97,189.36 36.45,189.36 36.75,189.05 40.06,189.05 v1(40.58,188.53)
F2_2: length 37.2
  TOP w0.254: v1(36.83,177.17) 37.27,177.17 38.54,175.89 U2.10 ; R10.1 v1(5.08,175.89)
  FLEX_1 w0.254: v1(5.08,175.89) 6.34,177.15 36.82,177.15 v1(36.83,177.17)
F2_3: length 36.7
  TOP w0.254: R17.1 v1(5.08,163.19) ; U3.10 v1(36.83,161.93)
  FLEX_1 w0.254: v1(5.08,163.19) 34.92,163.19 36.19,161.93 v1(36.83,161.93)
F2_4: length 37.2
  TOP w0.254: v1(36.83,151.76) 37.51,151.76 38.28,150.99 38.62,150.99 39.12,150.5 U4.10 ; R24.1 v1(5.08,150.5)
  FLEX_1 w0.254: v1(36.83,151.76) 6.35,151.76 v1(5.08,150.5)
F3_1: length 41.4
  TOP w0.254: R5.1 v1(4.95,183.51) ; v1(36.96,187.32) 37.37,186.91 37.69,186.91 38.54,186.06 U1.11
  FLEX_1 w0.254: v1(4.95,183.51) 4.95,186.56 7.11,188.72 35.56,188.72 v1(36.96,187.32)
F3_2: length 41.5
  TOP w0.254: U2.11 v1(36.19,174.62) ; R12.1 v1(5.08,170.81)
  FLEX_1 w0.254: v1(5.08,170.81) 5.08,174.62 6.98,176.53 33.65,176.53 35.56,174.62 v1(36.19,174.62)
F3_3: length 40.2
  TOP w0.254: R19.1 v1(5.08,158.12) ; U3.11 v1(36.19,160.66)
  FLEX_1 w0.254: v1(5.08,158.12) 5.08,160.66 6.98,162.56 34.29,162.56 v1(36.19,160.66)
F3_4: length 41.1
  TOP w0.254: R26.1 v1(5.08,145.41) ; U4.11 v1(36.83,149.22)
  FLEX_1 w0.254: v1(36.83,149.22) 35.56,149.22 33.65,151.13 7.62,151.13 5.08,148.59 v1(5.08,145.41)
F4_1: length 9.2
  TOP w0.254: 39.43,184.78 38.1,184.78 37.46,185.42 v1(37.46,186.06) ; R7.2 v1(37.46,180.97)
  FLEX_2 w0.254: v1(37.46,180.97) 37.46,181.87 37.39,181.95 37.39,183.17 37.46,183.25 v1(37.46,186.06)
F4_2: length 9
  TOP w0.254: R14.2 v1(37.59,168.28) ; U2.12 v1(37.46,173.36)
  FLEX_2 w0.254: v1(37.59,168.28) 36.75,169.11 36.75,172.01 37.46,172.72 v1(37.46,173.36)
F4_3: length 8.2
  TOP w0.254: R21.2 v1(37.59,155.57) ; v1(36.83,159.38) U3.12
  FLEX_2 w0.254: v1(36.83,159.38) 37.59,158.62 37.59,157.34 37.39,157.14 37.39,156.55 37.59,156.35 v1(37.59,155.57)
F4_4: length 9.3
  TOP w0.254: R28.2 v1(37.59,142.88) ; U4.12 v1(36.83,147.95)
  FLEX_2 w0.254: v1(36.83,147.95) 36.83,144.52 36.75,144.44 36.75,143.85 36.83,143.77 36.83,143.64 v1(37.59,142.88)
F5_1: length 3.3
  TOP w0.254: U1.13 38.4,183.51 38.37,183.54 37.83,183.54 37.8,183.51 R6.2
F5_2: length 4
  TOP w0.254: U2.13 38.1,172.08 37.46,171.45 v1(37.46,170.81) R13.2
F5_3: length 3.1
  TOP w0.254: R20.2 U3.13
F5_4: length 3.6
  TOP w0.254: U4.13 38.54,146.69 37.27,145.41 R27.2
F6_1: length 12.2
  TOP w0.254: v1(37.72,188.34) 37.46,188.59 R4.2 ; U1.15 38.4,180.97 37.74,181.64 37.19,181.64 v1(36.58,182.25)
  FLEX_2 w0.254: v1(37.72,188.34) 36.97,188.34 36.25,187.62 36.25,187.03 36.58,186.7 v1(36.58,182.25)
F6_2: length 10.5
  TOP w0.254: R11.2 v1(37.46,175.89) ; U2.15 v1(37.46,169.55)
  FLEX_2 w0.254: v1(37.46,175.89) 37.46,174.62 38.73,173.36 38.73,170.81 v1(37.46,169.55)
F6_3: length 10.1
  TOP w0.254: R18.2 v1(37.46,163.19) ; U3.15 38.54,155.57 38.1,156.02 v1(38.1,156.84)
  FLEX_2 w0.254: v1(38.1,156.84) 38.1,162.56 v1(37.46,163.19)
F6_4: length 10.4
  TOP w0.254: R25.2 v1(37.85,150.5) ; 39.43,144.14 v1(37.46,144.14)
  FLEX_2 w0.254: v1(37.46,144.14) 37.46,146.05 38.3,146.88 38.3,150.05 v1(37.85,150.5)
F7_1: length 12.9
  TOP w0.254: U1.14 v1(38.1,182.25) ; R2.2 v1(37.59,191.13)
  FLEX_2 w0.254: v1(37.59,191.13) 38.04,190.69 38.28,190.69 39.37,189.6 39.37,184.78 38.1,183.51 v1(38.1,182.25)
F7_2: length 12.7
  TOP w0.254: U2.14 40.39,170.81 40.64,171.07 40.64,177.8 40,178.44 38.04,178.44 37.96,178.51 37.48,178.51 37.4,178.44 R9.2
F7_3: length 12.3
  TOP w0.254: U3.14 39.75,156.84 40.25,157.34 40.25,157.51 40.4,157.66 40.4,163.65 39.58,164.47 38.73,164.47 37.46,165.74 R16.2
F7_4: length 12.6
  TOP w0.254: R23.2 40,153.03 40.64,152.4 40.64,145.73 40.32,145.41 U4.14
INT: length 361.7
  TOP w0.254: v1(42.55,146.69) U4.4 45.46,146.69 49.15,150.38 49.15,156.36 49.25,156.46 49.25,159.97 49.15,160.08 49.15,161.11 48.95,161.32 48.95,161.43 48.84,161.54 48.84,162.3 48.79,162.35 48.79,163.51 48.74,163.56 48.74,164.1 48.84,164.21 v1(48.84,164.85) ; v1(156.34,115.7) 157.4,116.76 159.89,116.76 ; U3.4 v1(42.55,158.12) ; U2.4 v1(42.55,172.08) ; 159.89,116.76 159.89,114.83 157.73,112.67 v1(157.73,110.36) 158.5,109.6 163.21,109.6 165.19,111.58 169.11,111.58 169.55,112.01 U9.6 ; 159.89,116.76 159.89,121.54 159.26,122.17 159.26,127.52 158.55,128.23 158.55,128.82 159.26,129.53 159.26,130.05 159.51,130.3 165.23,130.3 165.61,129.92 165.61,129.34 165.63,129.31 RV1.5 ; U1.4 v1(42.55,183.51)
  FLEX_1 w0.254: v1(140.84,118.24) 139.7,118.24 139.7,118.26 139.16,118.8 132.08,118.8 arc(114.6,126.03) 107.37,143.51 107.37,144.65 arc(101.59,158.61) 87.63,164.39 55.89,164.39 arc(55.47,164.45) 55.08,164.62 arc(54.69,164.79) 54.26,164.85 v1(48.84,164.85)
  FLEX_2 w0.254: v1(42.55,183.51) 42.55,181.61 41.91,180.97 41.91,172.72 v1(42.55,172.08) 42.55,170.81 41.91,170.18 41.91,158.75 v1(42.55,158.12) 42.55,156.21 41.27,154.94 41.27,149.86 41.91,149.22 41.91,147.32 v1(42.55,146.69)
  FLEX_2 w0.5: v1(157.73,110.36) 157.73,70.61 154.56,67.44 154.56,54.1 153.03,52.58 153.03,43.43 157.1,39.37 157.1,3.56
  INT_4 w0.254: v1(156.34,115.7) 152.4,115.7 151.33,116.76 150.32,116.76 149.61,117.47 141.22,117.47 140.84,117.86 v1(140.84,118.24)
INT3: length 85
  TOP w0.254: v1(160.4,127) 160.02,127 159.74,126.72 159.74,122.45 160.53,121.67 v1(160.53,113.79) 160.53,113.16 159.32,111.95 v1(158.43,111.95)
  FLEX_2 w0.5: v1(158.43,111.95) 157.9,111.41 156.71,111.41 156.01,110.71 156.01,110.02 156.97,109.06 156.97,70.99 152.91,66.93 152.91,60.33
  BOTTOM w0.254: v1(160.53,113.79) 160.15,114.17 D3.1 ; v1(160.4,127) 160.53,127.13 164.21,127.13 164.47,127.38 164.47,128.4 C15.1 163.14,129.72 163.14,129.85 R35.1
INT_N: length 195.5
  TOP w0.254: RV2.2 v1(162.59,151.54) ; v1(149.03,133.03) 149.33,132.74 149.33,131.56 148.58,130.81 145.04,130.81 143.56,129.33 143.56,114.12 146.69,111 v1(151.64,111)
  FLEX_1 w0.254: v1(162.59,151.54) 154.84,151.54 153.42,150.11 152.64,150.11 152.58,150.05 152.33,150.05 149.03,146.75 v1(149.03,133.03)
  FLEX_2 w0.5: 159.64,3.56 159.64,40.75 164.08,45.19 164.08,51.58 165.17,52.67 165.17,66.22 162.31,69.09 162.31,112.14 161.6,112.85 154.87,112.85 154.61,113.1 152.31,113.1 151.82,112.61 151.82,112.58 151.64,112.39 v1(151.64,111)
  BOTTOM w0.254: R32.2 157.23,152.4 158.12,151.51 161.98,151.51 162,151.54 v1(162.59,151.54)
LG1: length 6.3
  TOP w0.254: v1(168.91,124.08) 167.39,125.6 165.53,125.6 164.97,126.16 RV1.1
  BOTTOM w0.254: D1.1 v1(168.91,124.08)
LG2: length 13.5
  TOP w0.254: D2.2 172.97,119.63 172.34,120.27 170.81,120.27 170.05,121.03 170.05,124.33 167.64,126.75 RV1.3
LG3: length 5.6
  BOTTOM w0.254: D1.2 168.91,121.41 168.15,120.65 166.88,120.65 165.48,119.25 R30.1
LG4: length 3.8
  TOP w0.254: D2.1 v1(172.97,114.43)
  BOTTOM w0.254: R29.1 172.97,115.06 v1(172.97,114.43)
N1_1: length 3.8
  TOP w0.254: 12.22,191.13 R1.2
N1_2: length 3.8
  TOP w0.254: R8.2 DSP2.1
N1_3: length 3.8
  TOP w0.254: DSP3.1 R15.2
N1_4: length 3.8
  TOP w0.254: DSP4.1 R22.2
N2_1: length 3.8
  TOP w0.254: R3.2 DSP1.2
N2_2: length 3.8
  TOP w0.254: R10.2 DSP2.2
N2_3: length 3.8
  TOP w0.254: DSP3.2 R17.2
N2_4: length 3.8
  TOP w0.254: R24.2 DSP4.2
N3_1: length 3.8
  TOP w0.254: 12.22,183.51 R5.2
N3_2: length 3.8
  TOP w0.254: R12.2 DSP2.4
N3_3: length 3.8
  TOP w0.254: R19.2 DSP3.4
N3_4: length 3.8
  TOP w0.254: DSP4.4 R26.2
N4_1: length 3.6
  TOP w0.254: R7.1 DSP1.6
N4_2: length 3.6
  TOP w0.254: DSP2.6 R14.1
N4_3: length 3.6
  TOP w0.254: DSP3.6 R21.1
N4_4: length 3.6
  TOP w0.254: DSP4.6 R28.1
N5_1: length 3.5
  TOP w0.254: 31.22,183.51 R6.1
N5_2: length 3.6
  TOP w0.254: R13.1 DSP2.7
N5_3: length 3.6
  TOP w0.254: R20.1 DSP3.7
N5_4: length 3.6
  TOP w0.254: R27.1 DSP4.7
N6_1: length 3.6
  TOP w0.254: R4.1 DSP1.9
N6_2: length 3.6
  TOP w0.254: R11.1 DSP2.9
N6_3: length 3.6
  TOP w0.254: DSP3.9 R18.1
N6_4: length 3.6
  TOP w0.254: DSP4.9 R25.1
N7_1: length 3.6
  TOP w0.254: 31.22,191.13 R2.1
N7_2: length 3.6
  TOP w0.254: DSP2.10 R9.1
N7_3: length 3.6
  TOP w0.254: R16.1 DSP3.10
N7_4: length 3.6
  TOP w0.254: R23.1 DSP4.10
NET000: length 271.7
  TOP w0.254: v1(47.88,165.61) 47.88,162.71 48.29,162.31 48.29,161.45 48.49,161.25 48.49,160.81 48.64,160.66 48.64,159.94 48.79,159.79 48.79,159.24 48.64,159.09 48.64,158.29 48.79,158.14 48.79,156.97 48.64,156.82 48.64,151.32 45.28,147.95 U4.5 v1(43.18,147.95) ; U3.5 v1(43.18,159.38) ; U2.5 v1(43.18,173.36) ; 44.39,184.78 v1(43.18,184.78)
  FLEX_1 w0.254: v1(47.88,165.61) 47.93,165.66 arc(48.01,165.72) 48.11,165.74 54.48,165.74 arc(54.6,165.71) 54.7,165.64 54.99,165.36 arc(55.5,165.02) 56.1,164.9 87.63,164.9 arc(101.94,158.97) 107.87,144.65 107.87,143.51 arc(114.96,126.39) 132.08,119.3 139.37,119.3 139.62,119.05 141.54,119.05 v1(142.3,118.29)
  FLEX_2 w0.254: v1(43.18,184.78) 43.89,184.07 43.89,179.78 42.42,178.31 42.42,176.02 43.18,175.26 v1(43.18,173.36) 43.81,172.72 43.81,169.55 43.18,168.91 v1(43.18,159.38) 43.81,158.75 43.81,155.57 42.42,154.18 42.42,150.62 43.18,149.86 v1(43.18,147.95)
  FLEX_2 w0.5: 162.62,56.01 161.54,56.01 159,58.55 156.84,58.55 156.34,59.05 156.34,63.12 159.69,66.48 159.69,111.05 v1(160.53,111.89)
  INT_4 w0.254: v1(142.3,118.29) 149.93,118.29 151,117.22 158.62,117.22 159.69,116.15 159.69,112.73 v1(160.53,111.89)
NET001: length 111.8
  TOP w0.254: U6.15 148.72,121.16 147.83,122.05 144.53,122.05 144.02,122.56 144.02,126.37 144.53,126.87 147.95,126.87 148.72,127.63 U5.15 148.72,130.18 149.1,130.56 151.38,130.56 152.4,131.57 156.34,131.57 157.48,130.43 157.48,127.51 156.97,127 155.83,127 155.07,126.24 U5.7 155.07,122.81 155.7,122.17 156.21,122.17 157.23,121.16 157.23,118.24 155.07,116.08 U6.7 155.07,112.73 156.84,110.95 v1(156.84,110.36)
  FLEX_2 w0.5: 162.62,58.55 161.61,58.55 159.64,60.52 159.64,65.15 160.53,66.04 v1(160.53,110.36)
  INT_4 w0.254: v1(160.53,110.36) 159.65,111.24 157.21,111.24 156.84,110.87 v1(156.84,110.36)
NET002: length 122.4
  TOP w0.254: 151.12,151.92 151.12,151.13 151.5,150.76 v1(152.28,150.76) ; v1(148.46,132.08) 145.54,132.08 143.1,129.64 143.1,112.04 v1(144.14,111)
  FLEX_1 w0.254: v1(148.46,132.08) 148.34,132.21 148.34,132.65 148.27,132.72 148.27,133.35 148.34,133.41 148.34,146.81 v1(152.28,150.76)
  FLEX_2 w0.5: 157.67,54.74 156.66,54.74 155.63,55.76 155.63,67.11 158.86,70.34 v1(158.86,110.44)
  INT_4 w0.254: v1(144.14,111) 148.84,111 150.24,109.6 158.65,109.6 158.86,109.81 v1(158.86,110.44)
NET003: length 24.4
  TOP w0.254: U8.6 151.13,155.57 v1(151.13,155.57) ; R31.2 145.67,153.54 149.48,153.54 149.86,153.17 149.86,149.47 v1(148.46,148.08)
  BOTTOM w0.254: v1(148.46,148.08) 149.73,149.35 149.73,154.94 150.37,155.57 v1(151.13,155.57) 151.13,156.16 150.88,156.16 C7.2
NET004: length 40.9
  TOP w0.254: U5.9 v1(156.34,128.14) ; v1(171.83,113.28) 171.83,114.55 170.81,115.57 U9.8 ; v1(156.34,120.78) U6.9 ; v1(163.19,112.14) U9.1
  INT_4 w0.254: v1(163.19,112.14) 163.19,117.98 160.4,120.78 v1(156.34,120.78) v1(156.34,128.14)
  BOTTOM w0.254: v1(163.19,112.14) 165.99,112.14 166.62,111.51 168.78,111.51 170.56,113.28 v1(171.83,113.28)
NET005: length 18.9
  TOP w0.254: U9.4 U9.5 v1(168.27,112.27)
  BOTTOM w0.254: v1(168.27,112.27) 168.27,114.94 168.53,115.19 R29.2 168.53,116.59 167.39,117.73 162.43,117.73 R30.2 160.91,121.03 161.04,121.16 C9.1
Net_105: length 1.7
  TOP w0.254: v1(154.43,120.52) 154.75,120.52 155.07,120.21 155.07,119.32
SIG-IN: length 55
  FLEX_2 w0.5: 154.56,3.56 154.56,40 151.89,42.67 151.89,56.01 152.91,57.02
SIG_IN_N: length 134.4
  TOP w0.254: v1(163.19,110.87) 161.93,112.14 161.93,123.57 161.16,124.33 161.16,128.52 161.42,128.78 162.56,128.78 R33.2 163.7,128.65 164.08,128.27 164.08,127.89 164.36,127.61 165.3,127.61 165.63,127.28 RV1.2
  FLEX_2 w0.5: v1(163.19,110.87) 163.19,69.47 165.87,66.79 165.87,52.38 164.78,51.29 164.78,44.9 162.18,42.29 162.18,3.56
TM1: length 56.4
  TOP w0.254: RV2.5 v1(162.59,156.11)
  FLEX_1 w0.254: v1(149.99,132.59) 149.99,133.09 149.67,133.4 149.67,146.49 152.72,149.54 153.61,149.54 155.07,151 161.8,151 162.18,150.62 163.07,150.62 163.96,151.51 163.96,155.57 163.42,156.11 v1(162.59,156.11)
  INT_4 w0.254: v1(149.99,132.59) 150.5,132.08 v1(166.62,132.08)
  BOTTOM w0.254: v1(166.62,132.08) R39.2
TM2: length 24.5
  TOP w0.254: RV2.3 163.22,153.58 162.93,153.87 162.18,153.87 161.93,153.62 RV2.1 v1(160.78,153.03) 159.2,154.62 151.06,154.62 149.86,155.83 U8.7 149.86,157.56 149.56,157.86 146.69,157.86 R31.1
TM3: length 5.2
  TOP w0.254: U8.5 152.39,158.03 152.4,158.04 v1(152.4,158.62)
  BOTTOM w0.254: v1(152.4,158.62) 153.03,158.62 153.54,158.12 C12.2
TM4: length 9.5
  FLEX_2 w0.5: 157.67,50.93 155.96,50.93 155.57,50.55 155.57,47.24 158.25,47.24 158.37,47.12 159.51,47.12
TM5: length 11.7
  FLEX_2 w0.5: 155.57,43.94 154.18,45.34 154.18,51.18 155.19,52.2 157.67,52.2
TM6: length 76.5
  TOP w0.254: v1(160.4,123.83) 160.4,123.19 161.42,122.17 v1(161.42,111)
  FLEX_2 w0.5: 162.62,53.47 163.02,53.47 163.76,54.21 163.76,60.39 163.07,61.09 161.42,61.09 160.78,61.72 160.78,64.77 162.31,66.29 162.31,67.69 161.42,68.58 v1(161.42,111)
  BOTTOM w0.254: R37.2 160.4,124.59 v1(160.4,123.83)
TM7: length 13.1
  FLEX_2 w0.5: 162.62,52.2 163.7,52.2 164.47,52.96 164.47,60.83 162.31,62.99
VC1: length 14.9
  TOP w0.254: U9.3 165.74,114.94 164.47,116.2 163.19,116.2 162.43,116.97 162.43,121.11 162.69,121.36 165.28,121.36 v1(165.74,120.9)
  BOTTOM w0.254: v1(165.74,120.9) 165.74,121.16 166.37,121.79 C13.2
VC2: length 18.1
  TOP w0.254: U9.10 U9.9 169.55,117.79 v1(169.89,117.44)
  BOTTOM w0.254: v1(169.89,117.44) 171.29,117.44 171.83,117.98 R34.2 172.97,119.38 173.23,119.63 173.23,121.28 169.72,124.79 167.72,124.79 167,124.08 C13.1

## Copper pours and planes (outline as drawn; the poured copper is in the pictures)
GND on TOP: 1.27,201.93 2.76,205.52 6.35,207.01 45.08,207.01 48.68,205.52 50.16,201.93 50.16,199.26 49.05,196.57 46.35,195.45 31.88,195.45 29.18,194.34 28.07,191.64 28.07,141.35 29.18,138.66 31.88,137.54 46.35,137.54 49.05,136.43 50.16,133.73 50.16,133.35 48.68,129.76 45.08,128.27 6.35,128.27 2.76,129.76 1.27,133.35 1.27,133.73 2.39,136.43 5.08,137.54 11.56,137.54 14.25,138.66 15.37,141.35 15.37,191.64 14.25,194.34 11.56,195.45 5.08,195.45 2.39,196.57 1.27,199.26
GND on INT_1: 6.35,128.27 2.76,129.76 1.27,133.35 1.27,201.93 2.76,205.52 6.35,207.01 45.08,207.01 48.68,205.52 50.16,201.93 50.16,133.35 48.68,129.76 45.08,128.27
GND on INT_1: 146.55,108.59 145.41,109.72 144.28,108.59 144.28,107.81 139.56,107.81 139.56,110.49 139.37,111.29 138.84,111.92 138.84,130.65 139.37,131.28 139.56,132.08 139.56,134.75 143.64,134.75 143.64,133.99 144.78,132.85 145.91,133.99 145.91,144.14 145.21,145.85 143.51,146.55 139.56,146.55 139.56,162.06 175.39,162.06 175.39,158.12 176.1,156.41 177.8,155.71 184.15,155.71 185.4,156.23 185.92,157.48 185.92,158.75 186.15,159.29 186.69,159.52 190.5,159.52 191.04,159.29 191.27,158.75 191.27,149.86 191.04,149.32 190.5,149.09 186.69,149.09 186.15,149.32 185.92,149.86 185.92,150.5 185.4,151.75 184.15,152.26 177.8,152.26 176.1,151.56 175.39,149.86 175.39,146.55 154.94,146.55 153.24,145.85 152.53,144.14 152.53,133.99 153.67,132.85 154.81,133.99 154.81,134.75 175.39,134.75 175.39,107.81 172.58,107.81 172.58,108.59 171.45,109.72 170.31,108.59
GND on FLEX_1: 175.26,158.37 175.26,158.12 176,156.32 177.8,155.57 184.15,155.57 185.5,156.13 186.06,157.48 186.06,158.75 186.24,159.2 186.69,159.38 190.5,159.38 190.95,159.2 191.13,158.75 191.13,154.31 173.36,154.31 173.36,158.37
GND on FLEX_1: 170.31,108.2 170.31,9.32 169.4,8.68 169.05,7.62 169.4,6.56 170.31,5.92 170.31,0.66 170.16,0.5 146.71,0.5 146.55,0.66 146.55,5.92 147.47,6.56 147.82,7.62 147.47,8.68 146.55,9.32 146.55,108.2
GND on FLEX_2: outline of 104 points within 0.5,0.5 191.27,207.78 ; 1 cut-out
VCC on FLEX_1: 50.04,155.96 45.08,155.96 44.07,156.97 44.07,178.05 45.08,179.07 50.16,179.07 50.16,195.07 49.91,195.33 37.21,195.33 36.96,195.07 36.96,192.53 40,189.48 41.02,189.48 41.27,189.23 41.27,187.96 39.5,186.18 39.5,180.34 39.24,180.09 35.69,180.09 35.43,179.83 35.43,178.56 35.69,178.31 38.73,178.31 39.5,177.55 39.5,143.26 37.97,141.73 36.19,141.73 35.94,141.48 35.94,137.92 36.19,137.67 49.15,137.67 50.16,138.68 50.16,156.08
VCC on FLEX_1: 139.7,107.95 139.7,112.9 140.21,113.41 143.64,113.41 143.64,128.52 139.45,128.52 139.45,131.13 139.64,131.59 139.7,132.08 139.7,134.49 139.83,134.62 143.51,134.62 143.51,133.99 144.78,132.72 146.05,133.99 146.05,134.62 146.18,134.75 146.18,144.14 146.05,144.28 145.31,145.94 143.64,146.68 143.64,146.69 139.7,146.69 139.7,161.93 175.26,161.93 175.26,159.38 175.01,159.13 173.1,159.13 173.1,154.18 174.88,154.18 174.88,149.35 175.26,149.35 175.26,146.94 175.13,146.81 155.07,146.81 153.1,145.99 152.27,144.02 152.27,134.75 152.4,134.62 152.4,133.99 153.67,132.72 154.94,133.99 154.94,134.62 175.26,134.62 175.26,107.95 172.72,107.95 172.72,108.59 172.35,109.48 171.45,109.86 171.32,109.98 145.29,109.98 145.13,109.82 144.52,109.48 144.18,108.87 144.14,108.84 144.14,107.95 ; 1 cut-out
VCC on FLEX_1: 191.13,154.18 191.13,149.86 190.95,149.41 190.5,149.22 186.69,149.22 186.24,149.41 186.06,149.86 186.06,150.5 185.5,151.84 184.15,152.4 177.8,152.4 176,151.66 175.26,149.86 175.26,149.73 173.36,149.73 173.36,154.18
VCC on FLEX_2: 164.34,111.38 163.45,110.49 163.45,69.22 165.86,66.8 165.86,52.32 164.85,51.31 164.72,51.31 164.72,10.92 163.7,9.91 163.7,0.89 164.08,0.51 170.18,0.51 170.31,0.64 170.31,110.49 169.42,111.38
VCC on INT_4: 6.35,128.27 2.76,129.76 1.27,133.35 1.27,201.93 2.76,205.52 6.35,207.01 45.08,207.01 48.68,205.52 50.16,201.93 50.16,133.35 48.68,129.76 45.08,128.27

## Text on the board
XSECTION_CHART: *  SURFACE - 0 MM | * COVERLAY_TOP MASK - 0.2032 MM | * ADHESIVE_TOP MASK - 0.025 MM | L3 FLEX_1 CONDUCTOR - 0.03048 MM | *  DIELECTRIC - 0.0762 MM | L4 FLEX_2 CONDUCTOR - 0.03048 MM | * ADHESIVE_BOTTOM MASK - 0.025 MM | * COVERLAY_BOTTOM MASK - 0.2032 MM | * SOLDERMASK_TOP MASK - 0.015 MM | L1 TOP CONDUCTOR - 0.03048 MM | *  DIELECTRIC - 0.2032 MM | L2 INT_1 CONDUCTOR - 0.03048 MM | *  DIELECTRIC - 0.127 MM | L5 INT_4 CONDUCTOR - 0.03048 MM | L6 BOTTOM CONDUCTOR - 0.03048 MM | * SOLDERMASK_BOTTOM MASK - 0.015 MM | * GOLD_SOFT_BOTTOM MASK - 0.00356 MM | FLEX1 | __________ | 0.59356 MM | STACKUP TABLE | Unit = Millimeter | PRIMARY | 0.94948 MM | FLEX3 | 0.59712 MM | # | 1 | 2 | 3 | 4 | 5 | 6 | NAME | COVERLAY_TOP | ADHESIVE_TOP | SOLDERMASK_TOP | TOP | INT_1 | FLEX_1 | FLEX_2 | INT_4 | BOTTOM | SOLDERMASK_BOTTOM | ADHESIVE_BOTTOM | COVERLAY_BOTTOM | GOLD_SOFT_BOTTOM | TYPE | SURFACE | MASK | CONDUCTOR | DIELECTRIC | MATERIAL | AIR | POLYIMIDE | ADHESIVE_EPOXY | SOLDERMASK_FLEXIBLE_LPI | COPPER | FR-4 | POLYIMIDE_RIGID_5MIL | POLYIMIDE_FILM | GOLD_SOFT_BONDABLE | TOLERANCE | +0/-0 | TOTAL THICKNESS | ZONE NAME | 0 | 0.2032 | 0.025 | 0.0305 | 0.0762 | 0.0036 | 0.5971 | CONN_ZONE | 0.5936 | ZONE_1 | ZONE_3 | 0.015 | 0.127 | 0.9495 | 3-4 | 1-6
